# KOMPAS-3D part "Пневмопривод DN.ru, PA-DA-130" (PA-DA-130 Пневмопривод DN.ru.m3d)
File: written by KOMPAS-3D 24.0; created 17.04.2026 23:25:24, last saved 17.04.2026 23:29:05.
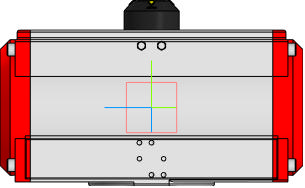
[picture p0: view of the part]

Document properties: Автор: DN.ru; Полное имя файла: C:\Работа\PA-DA-х Пневмопривод DN.ru\130\PA-DA-130 Пневмопривод DN.ru.m3d

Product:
- Part/product: Пневмопривод DN.ru  | designation PA-DA-130
    Масса: 8.9
    Раздел спецификации: Прочие изделия
    Примечание: D290-00297

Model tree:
1. Операция без истории:1

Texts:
  PA-DA-130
